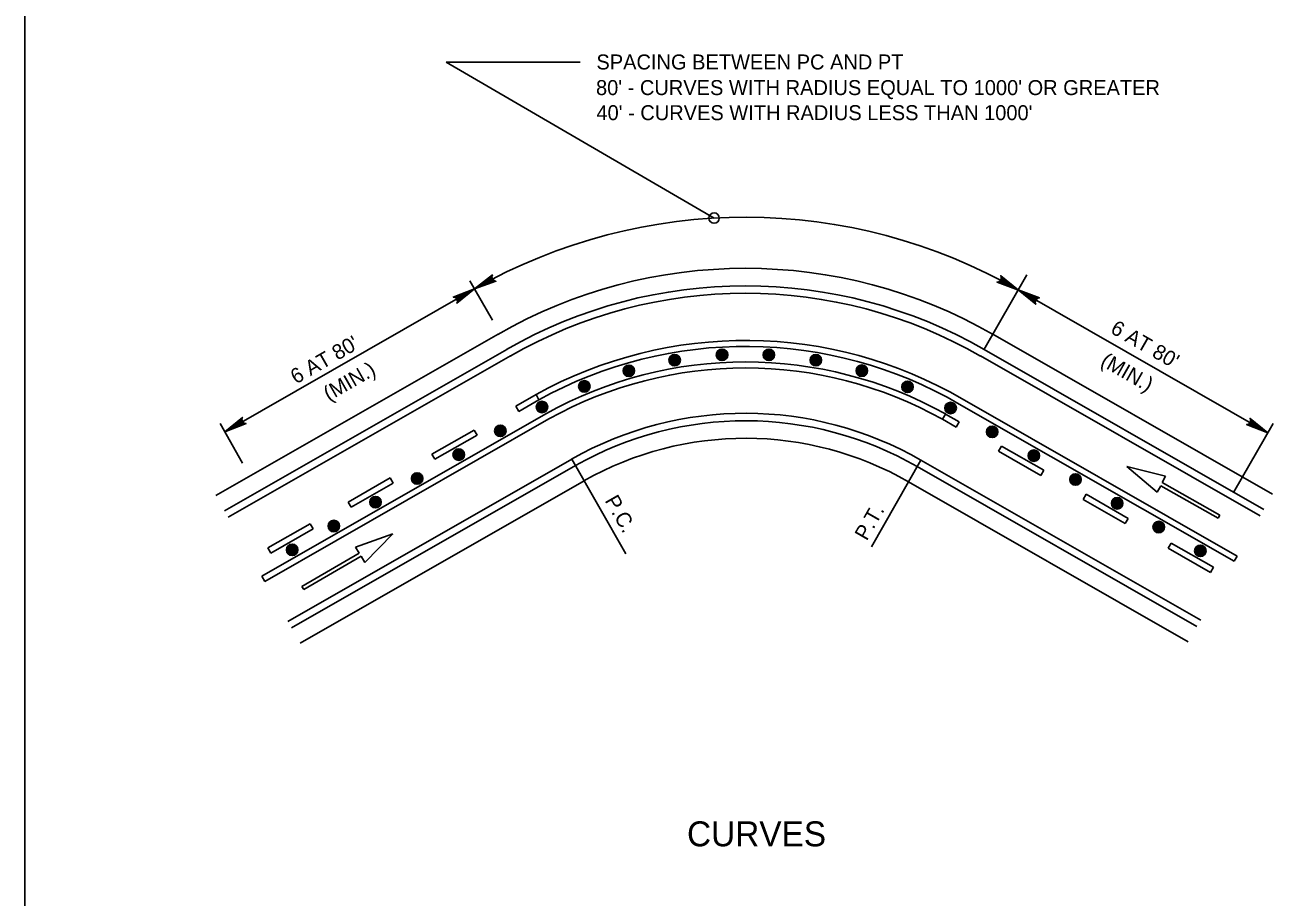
# Model space of a CAD drawing. Extents: x 639362 to 641108, y 298458 to 299646.
# Drawn here: x 640243.3 to 640493.4, y 299241.2 to 299415.8 of the extents above; entities that cross this region are included whole.
import ezdxf

# ---------------------------------------------------------------- set-up
doc = ezdxf.new("R2010")
doc.units = 0
doc.layers.add('1', color=7, linetype='Continuous')
doc.layers.add('2', color=7, linetype='Continuous')

msp = doc.modelspace()

# ---------------------------------------------------------------- linework, layer by layer
at = {"layer": '1'}
msp.add_line((640243.31, 299630.63), (640243.31, 299066.63), dxfattribs=at)
at = {"layer": '2'}
for p, q in [((640381.38, 299377.13), (640327.69, 299408.36)), ((640354.57, 299408.36), (640327.69, 299408.36)), ((640332.47, 299364.56), (640336.97, 299356.69)), ((640444.02, 299365.8), (640435.45, 299350.79)), ((640283.34, 299334.37), (640333.39, 299362.97)), ((640492.33, 299334.17), (640442.29, 299362.76)), ((640281.57, 299321.57), (640338.1, 299353.88)), ((640493.27, 299321.84), (640437.21, 299353.88)), ((640283.3, 299318.53), (640339.84, 299350.84)), ((640284.05, 299317.23), (640340.58, 299349.53)), ((640490.79, 299317.5), (640434.73, 299349.53)), ((640491.54, 299318.8), (640435.47, 299350.84)), ((640345.71, 299341.8), (640341.64, 299339.48)), ((640346.29, 299340.75), (640345.71, 299341.8)), ((640345.71, 299341.8), (640346.29, 299340.75)), ((640345.71, 299341.8), (640346.29, 299340.75)), ((640341.64, 299339.48), (640342.24, 299338.43)), ((640342.24, 299338.43), (640346.29, 299340.75)), ((640430.51, 299339.9), (640485.6, 299308.42)), ((640486.2, 299309.46), (640431.11, 299340.94)), ((640347.66, 299337.96), (640290.78, 299305.46)), ((640291.37, 299304.41), (640348.26, 299336.92)), ((640427.73, 299337.91), (640427.14, 299336.87)), ((640427.14, 299336.87), (640427.73, 299337.91)), ((640427.14, 299336.87), (640429.91, 299335.29)), ((640430.5, 299336.33), (640427.73, 299337.91)), ((640429.91, 299335.29), (640430.5, 299336.33)), ((640282.39, 299336.04), (640286.93, 299328.09)), ((640324.85, 299329.88), (640333.31, 299334.71)), ((640333.91, 299333.67), (640325.44, 299328.84)), ((640333.31, 299334.71), (640333.91, 299333.67)), ((640493.37, 299336), (640485.47, 299322.17)), ((640438.37, 299330.45), (640438.96, 299331.5)), ((640438.96, 299331.5), (640447.43, 299326.66)), ((640295.97, 299296.37), (640352.85, 299328.88)), ((640325.44, 299328.84), (640324.85, 299329.88)), ((640363.69, 299309.92), (640352.85, 299328.88)), ((640422.82, 299328.68), (640412.91, 299311.35)), ((640478.88, 299296.65), (640422.82, 299328.68)), ((640446.83, 299325.62), (640438.37, 299330.45)), ((640296.71, 299295.07), (640353.6, 299327.58)), ((640478.13, 299295.35), (640422.07, 299327.38)), ((640447.43, 299326.66), (640446.83, 299325.62)), ((640464.08, 299327.42), (640470.14, 299322.29)), ((640471.84, 299325.46), (640464.08, 299327.42)), ((640298.45, 299292.03), (640355.33, 299324.54)), ((640308.05, 299320.28), (640316.51, 299325.12)), ((640317.11, 299324.07), (640308.65, 299319.24)), ((640316.51, 299325.12), (640317.11, 299324.07)), ((640476.4, 299292.31), (640420.34, 299324.34)), ((640471.13, 299324.2), (640471.84, 299325.46)), ((640482.73, 299317.64), (640471.13, 299324.2)), ((640455.3, 299320.8), (640455.9, 299321.84)), ((640455.9, 299321.84), (640464.36, 299317)), ((640470.14, 299322.29), (640470.86, 299323.55)), ((640470.86, 299323.55), (640482.38, 299317.03)), ((640308.65, 299319.24), (640308.05, 299320.28)), ((640463.77, 299315.96), (640455.3, 299320.8)), ((640464.36, 299317), (640463.77, 299315.96)), ((640482.38, 299317.03), (640482.73, 299317.64)), ((640291.99, 299311.1), (640300.46, 299315.94)), ((640301.05, 299314.9), (640292.59, 299310.06)), ((640300.46, 299315.94), (640301.05, 299314.9)), ((640317.04, 299313.9), (640309.55, 299311.27)), ((640311.42, 299308.2), (640317.04, 299313.9)), ((640292.59, 299310.06), (640291.99, 299311.1)), ((640309.55, 299311.27), (640310.27, 299310.02)), ((640472.38, 299311.02), (640472.98, 299312.06)), ((640472.98, 299312.06), (640481.44, 299307.23)), ((640310.27, 299310.02), (640298.81, 299303.38)), ((640299.17, 299302.77), (640310.7, 299309.45)), ((640310.7, 299309.45), (640311.42, 299308.2)), ((640480.85, 299306.18), (640472.38, 299311.02)), ((640485.6, 299308.42), (640486.2, 299309.46)), ((640481.44, 299307.23), (640480.85, 299306.18)), ((640290.78, 299305.46), (640291.37, 299304.41)), ((640298.81, 299303.38), (640299.17, 299302.77))]:
    msp.add_line(p, q, dxfattribs=at)
for points in [[(640337.39, 299364.56), (640337.1, 299364.76), (640333.39, 299362.97), (640337.39, 299364.56), (640337.68, 299364.5), (640333.39, 299362.97), (640336.89, 299365.13), (640336.88, 299365.47), (640333.39, 299362.97), (640336.98, 299365.77), (640336.88, 299365.47)], [(640438.92, 299365.32), (640438.9, 299364.97), (640442.36, 299362.73), (640438.92, 299365.32), (640438.82, 299365.59), (640442.36, 299362.73), (640438.69, 299364.59), (640438.41, 299364.4), (640442.36, 299362.73), (640438.1, 299364.34), (640438.41, 299364.4)], [(640329.41, 299361.28), (640329.71, 299361.09), (640333.39, 299362.97), (640329.41, 299361.28), (640329.13, 299361.33), (640333.39, 299362.97), (640329.93, 299360.72), (640329.95, 299360.38), (640333.39, 299362.97), (640329.85, 299360.09), (640329.95, 299360.38)], [(640445.74, 299360.17), (640445.75, 299360.52), (640442.29, 299362.76), (640445.74, 299360.17), (640445.83, 299359.9), (640442.29, 299362.76), (640445.96, 299360.89), (640446.25, 299361.08), (640442.29, 299362.76), (640446.55, 299361.15), (640446.25, 299361.08)], [(640287.32, 299336.04), (640287.03, 299336.23), (640283.34, 299334.37), (640287.32, 299336.04), (640287.61, 299335.99), (640283.34, 299334.37), (640286.81, 299336.6), (640286.79, 299336.95), (640283.34, 299334.37), (640286.89, 299337.24), (640286.79, 299336.95)], [(640488.88, 299336.76), (640488.86, 299336.41), (640492.33, 299334.17), (640488.88, 299336.76), (640488.78, 299337.03), (640492.33, 299334.17), (640488.65, 299336.03), (640488.37, 299335.84), (640492.33, 299334.17), (640488.06, 299335.78), (640488.37, 299335.84)]]:
    msp.add_lwpolyline(points, dxfattribs=at)
for centre, radius in [((640381.38, 299377.13), 1.04), ((640373.49, 299348.69), 1.15), ((640373.49, 299348.69), 1.07), ((640373.49, 299348.69), 0.985), ((640373.49, 299348.69), 0.904), ((640373.49, 299348.69), 0.822), ((640373.49, 299348.69), 0.741), ((640373.49, 299348.69), 0.659), ((640373.49, 299348.69), 0.578), ((640373.49, 299348.69), 0.496), ((640373.49, 299348.69), 0.414), ((640373.49, 299348.69), 0.333), ((640373.49, 299348.69), 0.251), ((640373.49, 299348.69), 0.17), ((640373.49, 299348.69), 0.0881), ((640382.98, 299349.77), 1.15), ((640382.98, 299349.77), 1.07), ((640382.98, 299349.77), 0.985), ((640382.98, 299349.77), 0.904), ((640382.98, 299349.77), 0.822), ((640382.98, 299349.77), 0.741), ((640382.98, 299349.77), 0.659), ((640382.98, 299349.77), 0.578), ((640382.98, 299349.77), 0.496), ((640382.98, 299349.77), 0.414), ((640382.98, 299349.77), 0.333), ((640382.98, 299349.77), 0.251), ((640382.98, 299349.77), 0.17), ((640382.98, 299349.77), 0.0881), ((640392.37, 299349.77), 1.15), ((640392.37, 299349.77), 1.07), ((640392.37, 299349.77), 0.985), ((640392.37, 299349.77), 0.904), ((640392.37, 299349.77), 0.822), ((640392.37, 299349.77), 0.741), ((640392.37, 299349.77), 0.659), ((640392.37, 299349.77), 0.578), ((640392.37, 299349.77), 0.496), ((640392.37, 299349.77), 0.414), ((640392.37, 299349.77), 0.333), ((640392.37, 299349.77), 0.251), ((640392.37, 299349.77), 0.17), ((640392.37, 299349.77), 0.0881), ((640401.78, 299348.7), 1.15), ((640401.78, 299348.7), 1.07), ((640401.78, 299348.7), 0.985), ((640401.78, 299348.7), 0.904), ((640401.78, 299348.7), 0.822), ((640401.78, 299348.7), 0.741), ((640401.78, 299348.7), 0.659), ((640401.78, 299348.7), 0.578), ((640401.78, 299348.7), 0.496), ((640401.78, 299348.7), 0.414), ((640401.78, 299348.7), 0.333), ((640401.78, 299348.7), 0.251), ((640401.78, 299348.7), 0.17), ((640401.78, 299348.7), 0.0881), ((640364.31, 299346.57), 1.15), ((640364.31, 299346.57), 1.07), ((640364.31, 299346.57), 0.985), ((640364.31, 299346.57), 0.904), ((640364.31, 299346.57), 0.822), ((640364.31, 299346.57), 0.741), ((640364.31, 299346.57), 0.659), ((640364.31, 299346.57), 0.578), ((640364.31, 299346.57), 0.496), ((640364.31, 299346.57), 0.414), ((640364.31, 299346.57), 0.333), ((640364.31, 299346.57), 0.251), ((640364.31, 299346.57), 0.17), ((640364.31, 299346.57), 0.0881), ((640410.99, 299346.58), 1.15), ((640410.99, 299346.58), 1.07), ((640410.99, 299346.58), 0.985), ((640410.99, 299346.58), 0.904), ((640410.99, 299346.58), 0.822), ((640410.99, 299346.58), 0.741), ((640410.99, 299346.58), 0.659), ((640410.99, 299346.58), 0.578), ((640410.99, 299346.58), 0.496), ((640410.99, 299346.58), 0.414), ((640410.99, 299346.58), 0.333), ((640410.99, 299346.58), 0.251), ((640410.99, 299346.58), 0.17), ((640410.99, 299346.58), 0.0881), ((640355.39, 299343.44), 1.15), ((640355.39, 299343.44), 1.07), ((640355.39, 299343.44), 0.985), ((640355.39, 299343.44), 0.904), ((640355.39, 299343.44), 0.822), ((640355.39, 299343.44), 0.741), ((640355.39, 299343.44), 0.659), ((640355.39, 299343.44), 0.578), ((640355.39, 299343.44), 0.496), ((640355.39, 299343.44), 0.414), ((640355.39, 299343.44), 0.333), ((640355.39, 299343.44), 0.251), ((640355.39, 299343.44), 0.17), ((640420.15, 299343.35), 1.15), ((640420.15, 299343.35), 1.07), ((640420.15, 299343.35), 0.985), ((640420.15, 299343.35), 0.904), ((640420.15, 299343.35), 0.822), ((640420.15, 299343.35), 0.741), ((640420.15, 299343.35), 0.659), ((640420.15, 299343.35), 0.578), ((640420.15, 299343.35), 0.496), ((640420.15, 299343.35), 0.414), ((640420.15, 299343.35), 0.333), ((640420.15, 299343.35), 0.251), ((640355.39, 299343.44), 0.0881), ((640420.15, 299343.35), 0.17), ((640420.15, 299343.35), 0.0881), ((640346.9, 299339.31), 1.15), ((640346.9, 299339.31), 1.07), ((640346.9, 299339.31), 0.985), ((640346.9, 299339.31), 0.904), ((640346.9, 299339.31), 0.822), ((640346.9, 299339.31), 0.741), ((640346.9, 299339.31), 0.659), ((640346.9, 299339.31), 0.578), ((640346.9, 299339.31), 0.496), ((640346.9, 299339.31), 0.414), ((640346.9, 299339.31), 0.333), ((640346.9, 299339.31), 0.251), ((640346.9, 299339.31), 0.17), ((640346.9, 299339.31), 0.0881), ((640428.77, 299339.11), 1.15), ((640428.77, 299339.11), 1.07), ((640428.77, 299339.11), 0.985), ((640428.77, 299339.11), 0.904), ((640428.77, 299339.11), 0.822), ((640428.77, 299339.11), 0.741), ((640428.77, 299339.11), 0.659), ((640428.77, 299339.11), 0.578), ((640428.77, 299339.11), 0.496), ((640428.77, 299339.11), 0.414), ((640428.77, 299339.11), 0.333), ((640428.77, 299339.11), 0.251), ((640428.77, 299339.11), 0.17), ((640428.77, 299339.11), 0.0881), ((640338.56, 299334.54), 1.15), ((640338.56, 299334.54), 1.07), ((640338.56, 299334.54), 0.985), ((640338.56, 299334.54), 0.904), ((640338.56, 299334.54), 0.822), ((640338.56, 299334.54), 0.741), ((640338.56, 299334.54), 0.659), ((640338.56, 299334.54), 0.578), ((640338.56, 299334.54), 0.496), ((640338.56, 299334.54), 0.414), ((640338.56, 299334.54), 0.333), ((640338.56, 299334.54), 0.251), ((640338.56, 299334.54), 0.17), ((640338.56, 299334.54), 0.0881), ((640437.11, 299334.34), 1.15), ((640437.11, 299334.34), 1.07), ((640437.11, 299334.34), 0.985), ((640437.11, 299334.34), 0.904), ((640437.11, 299334.34), 0.822), ((640437.11, 299334.34), 0.741), ((640437.11, 299334.34), 0.659), ((640437.11, 299334.34), 0.578), ((640437.11, 299334.34), 0.496), ((640437.11, 299334.34), 0.414), ((640437.11, 299334.34), 0.333), ((640437.11, 299334.34), 0.251), ((640437.11, 299334.34), 0.17), ((640437.11, 299334.34), 0.0881), ((640330.22, 299329.78), 1.15), ((640330.22, 299329.78), 1.07), ((640330.22, 299329.78), 0.985), ((640330.22, 299329.78), 0.904), ((640330.22, 299329.78), 0.822), ((640330.22, 299329.78), 0.741), ((640330.22, 299329.78), 0.659), ((640330.22, 299329.78), 0.578), ((640330.22, 299329.78), 0.496), ((640330.22, 299329.78), 0.414), ((640330.22, 299329.78), 0.333), ((640330.22, 299329.78), 0.251), ((640330.22, 299329.78), 0.17), ((640330.22, 299329.78), 0.0881), ((640445.45, 299329.57), 1.15), ((640445.45, 299329.57), 1.07), ((640445.45, 299329.57), 0.985), ((640445.45, 299329.57), 0.904), ((640445.45, 299329.57), 0.822), ((640445.45, 299329.57), 0.741), ((640445.45, 299329.57), 0.659), ((640445.45, 299329.57), 0.578), ((640445.45, 299329.57), 0.496), ((640445.45, 299329.57), 0.414), ((640445.45, 299329.57), 0.333), ((640445.45, 299329.57), 0.251), ((640445.45, 299329.57), 0.17), ((640445.45, 299329.57), 0.0881), ((640321.88, 299325.01), 1.15), ((640321.88, 299325.01), 1.07), ((640321.88, 299325.01), 0.985), ((640321.88, 299325.01), 0.904), ((640321.88, 299325.01), 0.822), ((640321.88, 299325.01), 0.741), ((640321.88, 299325.01), 0.659), ((640321.88, 299325.01), 0.578), ((640321.88, 299325.01), 0.496), ((640321.88, 299325.01), 0.414), ((640321.88, 299325.01), 0.333), ((640321.88, 299325.01), 0.251), ((640321.88, 299325.01), 0.17), ((640321.88, 299325.01), 0.0881), ((640453.79, 299324.81), 1.15), ((640453.79, 299324.81), 1.07), ((640453.79, 299324.81), 0.985), ((640453.79, 299324.81), 0.904), ((640453.79, 299324.81), 0.822), ((640453.79, 299324.81), 0.741), ((640453.79, 299324.81), 0.659), ((640453.79, 299324.81), 0.578), ((640453.79, 299324.81), 0.496), ((640453.79, 299324.81), 0.414), ((640453.79, 299324.81), 0.333), ((640453.79, 299324.81), 0.251), ((640453.79, 299324.81), 0.17), ((640453.79, 299324.81), 0.0881), ((640313.54, 299320.25), 1.15), ((640313.54, 299320.25), 1.07), ((640313.54, 299320.25), 0.985), ((640313.54, 299320.25), 0.904), ((640313.54, 299320.25), 0.822), ((640462.13, 299320.04), 1.15), ((640462.13, 299320.04), 1.07), ((640313.54, 299320.25), 0.741), ((640313.54, 299320.25), 0.659), ((640313.54, 299320.25), 0.578), ((640313.54, 299320.25), 0.496), ((640313.54, 299320.25), 0.414), ((640313.54, 299320.25), 0.333), ((640313.54, 299320.25), 0.251), ((640313.54, 299320.25), 0.17), ((640313.54, 299320.25), 0.0881), ((640462.13, 299320.04), 0.985), ((640462.13, 299320.04), 0.904), ((640462.13, 299320.04), 0.822), ((640462.13, 299320.04), 0.741), ((640462.13, 299320.04), 0.659), ((640462.13, 299320.04), 0.578), ((640462.13, 299320.04), 0.496), ((640462.13, 299320.04), 0.414), ((640462.13, 299320.04), 0.333), ((640462.13, 299320.04), 0.251), ((640462.13, 299320.04), 0.17), ((640462.13, 299320.04), 0.0881), ((640305.2, 299315.48), 1.15), ((640305.2, 299315.48), 1.07), ((640305.2, 299315.48), 0.985), ((640305.2, 299315.48), 0.904), ((640305.2, 299315.48), 0.822), ((640305.2, 299315.48), 0.741), ((640305.2, 299315.48), 0.659), ((640305.2, 299315.48), 0.578), ((640470.47, 299315.28), 1.15), ((640470.47, 299315.28), 1.07), ((640470.47, 299315.28), 0.985), ((640470.47, 299315.28), 0.904), ((640470.47, 299315.28), 0.822), ((640305.2, 299315.48), 0.496), ((640305.2, 299315.48), 0.414), ((640305.2, 299315.48), 0.333), ((640305.2, 299315.48), 0.251), ((640305.2, 299315.48), 0.17), ((640305.2, 299315.48), 0.0881), ((640470.47, 299315.28), 0.741), ((640470.47, 299315.28), 0.659), ((640470.47, 299315.28), 0.578), ((640470.47, 299315.28), 0.496), ((640470.47, 299315.28), 0.414), ((640470.47, 299315.28), 0.333), ((640470.47, 299315.28), 0.251), ((640470.47, 299315.28), 0.17), ((640470.47, 299315.28), 0.0881), ((640296.86, 299310.72), 1.15), ((640296.86, 299310.72), 1.07), ((640296.86, 299310.72), 0.985), ((640296.86, 299310.72), 0.904), ((640296.86, 299310.72), 0.822), ((640296.86, 299310.72), 0.741), ((640296.86, 299310.72), 0.659), ((640296.86, 299310.72), 0.578), ((640296.86, 299310.72), 0.496), ((640296.86, 299310.72), 0.414), ((640478.81, 299310.51), 1.15), ((640478.81, 299310.51), 1.07), ((640478.81, 299310.51), 0.985), ((640478.81, 299310.51), 0.904), ((640478.81, 299310.51), 0.822), ((640478.81, 299310.51), 0.741), ((640478.81, 299310.51), 0.659), ((640478.81, 299310.51), 0.578), ((640296.86, 299310.72), 0.333), ((640296.86, 299310.72), 0.251), ((640296.86, 299310.72), 0.17), ((640296.86, 299310.72), 0.0881), ((640478.81, 299310.51), 0.496), ((640478.81, 299310.51), 0.414), ((640478.81, 299310.51), 0.333), ((640478.81, 299310.51), 0.251), ((640478.81, 299310.51), 0.17), ((640478.81, 299310.51), 0.0881)]:
    msp.add_circle(centre, radius, dxfattribs=at)
for centre, radius, start, end in [((640387.66, 299267.45), 109.86, 60.1371, 119.6067), ((640387.66, 299267.45), 99.63, 60.1372, 119.8628), ((640387.66, 299267.45), 96.13, 60.1372, 119.8628), ((640387.66, 299267.45), 94.63, 60.1372, 119.8628), ((640387.65, 299266.03), 86.61, 59.8818, 118.9662), ((640387.65, 299266.03), 85.41, 59.8819, 118.9663), ((640387.66, 299266.01), 82.32, 60.8663, 119.0641), ((640387.66, 299266.02), 81.11, 60.8699, 119.0594), ((640387.66, 299267.45), 70.61, 60.1372, 119.5398), ((640387.66, 299267.45), 69.11, 60.1372, 119.5398), ((640387.66, 299267.45), 65.61, 60.1372, 119.5398)]:
    msp.add_arc(centre, radius, start, end, dxfattribs=at)

# ---------------------------------------------------------------- texts
for s, height, p in [('SPACING BETWEEN PC AND PT', 3, (640357.81, 299406.89)), ("80' - CURVES WITH RADIUS EQUAL TO 1000' OR GREATER", 3, (640357.73, 299401.76)), ("40' - CURVES WITH RADIUS LESS THAN 1000'", 3, (640357.81, 299396.74)), ('CURVES', 5, (640375.96, 299251.36))]:
    msp.add_text(s, height=height, dxfattribs=at).set_placement(p)
for s, rotation, p in [("6 AT 80'", 330.2559, (640460.59, 299354.26)), ("6 AT 80'", 29.7453, (640297.61, 299343.82)), ('(MIN.)', 330.2559, (640458.59, 299347.75)), ('(MIN.)', 29.7453, (640304.2, 299340.41)), ('P.C.', 299.7361, (640359.39, 299320.6)), ('P.T.', 60.2574, (640411.97, 299312.38))]:
    msp.add_text(s, height=3, rotation=rotation, dxfattribs=at).set_placement(p)

doc.saveas('drawing.dxf')
